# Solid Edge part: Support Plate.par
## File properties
Author: davee
Template: Normal.par
Last saved by: davee
Revision: 15
Application: Solid Edge
Accuracy: 0.990
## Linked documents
MH Die Plate.par
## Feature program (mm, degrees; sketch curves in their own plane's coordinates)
sketch for "ExtrudedProtrusion_1" #1 plane through (0, 0, 0) normal (0, 0, 1) x-axis (1, 0, 0)
  circle centre (-80, 49) radius 5.053
sketch for "ExtrudedProtrusion_1" #2 plane through (0, 0, 0) normal (0, 0, 1) x-axis (1, 0, 0)
  circle centre (-80, -49) radius 5.053
sketch for "ExtrudedProtrusion_1" #3 plane through (0, 0, 0) normal (0, 0, 1) x-axis (1, 0, 0)
  circle centre (80, -49) radius 5.053
sketch for "ExtrudedProtrusion_1" #4 plane through (0, 0, 0) normal (0, 0, 1) x-axis (1, 0, 0)
  circle centre (0, 95) radius 3
sketch for "ExtrudedProtrusion_1" #5 plane through (0, 0, 0) normal (0, 0, 1) x-axis (1, 0, 0)
  circle centre (80, 49) radius 5.053
sketch for "ExtrudedProtrusion_1" #6 plane through (0, 0, 0) normal (0, 0, 1) x-axis (1, 0, 0)
  line (100, 100) -> (-100, 100)
  line (-100, 100) -> (-100, -100)
  line (-100, -100) -> (100, -100)
  line (100, -100) -> (100, 100)
  dimension (linear) = 100
  dimension (linear) = 100
extrude "ExtrudedProtrusion_1" add finite 39.08 along -normal
sketch for "ExtrudedCutout_1" #1 plane through (0, 0, 0) normal (0, 0, 1) x-axis (1, 0, 0)
  circle centre (-80, 49) radius 6.25
sketch for "ExtrudedCutout_1" #2 plane through (0, 0, 0) normal (0, 0, 1) x-axis (1, 0, 0)
  circle centre (80, 49) radius 6.25
sketch for "ExtrudedCutout_1" #3 plane through (0, 0, 0) normal (0, 0, 1) x-axis (1, 0, 0)
  circle centre (80, -49) radius 6.25
sketch for "ExtrudedCutout_1" #4 plane through (0, 0, 0) normal (0, 0, 1) x-axis (1, 0, 0)
  circle centre (-80, -49) radius 6.25
extrude "ExtrudedCutout_1" cut finite 60.325 along -normal
sketch for "ExtrudedCutout_2" #1 plane through (0, 0, -39.08) normal (0, 0, -1) x-axis (-1, 0, 0)
  circle centre (40, 85) radius 5.25
sketch for "ExtrudedCutout_2" #2 plane through (0, 0, -39.08) normal (0, 0, -1) x-axis (-1, 0, 0)
  circle centre (-25.3, 74) radius 1.75
sketch for "ExtrudedCutout_2" #3 plane through (0, 0, -39.08) normal (0, 0, -1) x-axis (-1, 0, 0)
  circle centre (-13.1725, 74) radius 1.75
sketch for "ExtrudedCutout_2" #4 plane through (0, 0, -39.08) normal (0, 0, -1) x-axis (-1, 0, 0)
  circle centre (25.3, 74) radius 1.75
sketch for "ExtrudedCutout_2" #5 plane through (0, 0, -39.08) normal (0, 0, -1) x-axis (-1, 0, 0)
  circle centre (-22, 13) radius 3.25
sketch for "ExtrudedCutout_2" #6 plane through (0, 0, -39.08) normal (0, 0, -1) x-axis (-1, 0, 0)
  circle centre (22, 13) radius 3.25
sketch for "ExtrudedCutout_2" #7 plane through (0, 0, -39.08) normal (0, 0, -1) x-axis (-1, 0, 0)
  circle centre (0, 0) radius 3.25
sketch for "ExtrudedCutout_2" #8 plane through (0, 0, -39.08) normal (0, 0, -1) x-axis (-1, 0, 0)
  circle centre (-40, -85) radius 5.25
sketch for "ExtrudedCutout_2" #9 plane through (0, 0, -39.08) normal (0, 0, -1) x-axis (-1, 0, 0)
  circle centre (40, -85) radius 5.25
sketch for "ExtrudedCutout_2" #10 plane through (0, 0, -39.08) normal (0, 0, -1) x-axis (-1, 0, 0)
  arc centre (13.172, 74) radius 1.75 from (11.4226, 74.0452) to (11.4226, 73.9548) cw
  line (11.4226, 74.0452) -> (11.4226, 73.9548)
sketch for "ExtrudedCutout_2" #11 plane through (0, 0, -39.08) normal (0, 0, -1) x-axis (-1, 0, 0)
extrude "ExtrudedCutout_2" cut finite 114.3 along -normal
sketch for "Hole_5" plane through (0, 0, -39.08) normal (0, 0, -1) x-axis (-1, 0, 0)
hole "Hole_5" diameter 6.5 through  CounterBoreDepth = 6.5 mm; VBottomAngle = 118 deg
sketch for "Hole_6" plane through (0, 100, -19.54) normal (0, 1, 0) x-axis (-1, 0, 0)
hole "Hole_6" diameter 8 finite  VBottomAngle = 118 deg
sketch for "unnamed Hole 1" plane through (0, 100, -19.54) normal (0, 1, 0) x-axis (-1, 0, 0)
  hole centre (-20, -4.04) bore radius 4
hole "unnamed Hole 1" finite
pattern "unnamed Pattern 1" of "Hole_6", "unnamed Hole 1"
sketch for "Hole_8" plane through (0, 100, -19.54) normal (0, 1, 0) x-axis (-1, 0, 0)
  hole centre (50, -4.04) bore radius 3.3235
hole "Hole_8" finite  ThreadDepth = 2 mm
sketch for "unnamed Hole 2" plane through (0, 100, -19.54) normal (0, 1, 0) x-axis (-1, 0, 0)
hole "unnamed Hole 2" finite
pattern "unnamed Pattern 2" of "Hole_8", "unnamed Hole 2"
Other named dimensions: "CopyConstruction_1": YScale = 1; ZScale = 1
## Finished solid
Body 1: solid body, 34 faces, 60 edges, 12 vertices.
  Faces by surface: cylinder 22, plane 10, cone 2
  Edges by curve: circle 44, line 16
Body 2: solid body, 236 faces, 512 edges, 273 vertices.
  Faces by surface: plane 103, cylinder 73, cone 20, torus 20, spline 6, swept 6, sphere 4, spun 4
  Edges by curve: line 288, circle 174, curve on surface 18, spline 18, intersection 8, ellipse 6
Bounding box of the edges (mm; curved faces can reach further): 200.000 x 200.000 x 41.110, from (-100, -100, -39.08) to (100, 100, 2.03).
Cylindrical faces by radius (mm): R0.7575 x4, R0.808 x6, R1.01 x9, R1.1165 x2, R1.5 x4, R1.515 x2, R1.6747 x2, R1.75 x4, R2.03 x14, R2.233 x2, R3 x4, R3.03 x3, R3.045 x2, R3.25 x4, R3.3235 x2, R4 x2, R5 x4, R5.053 x4, R5.25 x4, R5.5 x1, R6.25 x4, R7 x1, R10 x1, R10.15 x1, R13.5 x4, R16 x4, R25.8825 x1
Conical faces (half-angle, radius in mm at the cone's reference point): 1 deg R1.7675 x2, 1 deg R2.424 x2, 3 deg R1.515 x8, 3 deg R3.8099 x1, 3 deg R3.8205 x1, 59 deg R2.233 x2, 59 deg R4 x2, 59 deg R5.053 x4
Toroidal faces (ring radius, tube radius in mm): R0.505 r1.01 x2, R0.7575 r0.7575 x2, R2.02 r1.01 x2, R2.2725 r0.7575 x2, R2.2818 r0.808 x8, R3.0431 r0.808 x1, R3.0538 r0.808 x1, R5.43 r1.01 x1, R5.4406 r1.01 x1
Spherical faces by radius (mm): R2.03 x4
Planar faces by outward normal: +x 14, +y 14, +z 29, -x 14, -y 14, -z 10, oblique 18
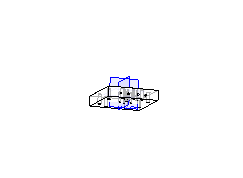
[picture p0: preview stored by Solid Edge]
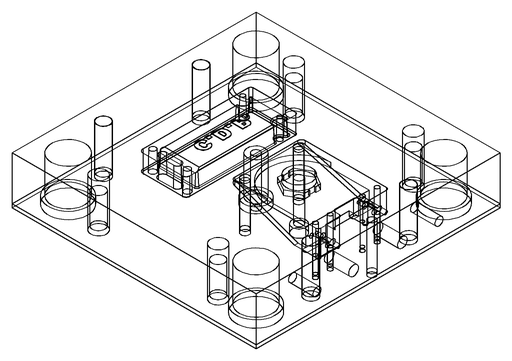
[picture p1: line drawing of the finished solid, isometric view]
